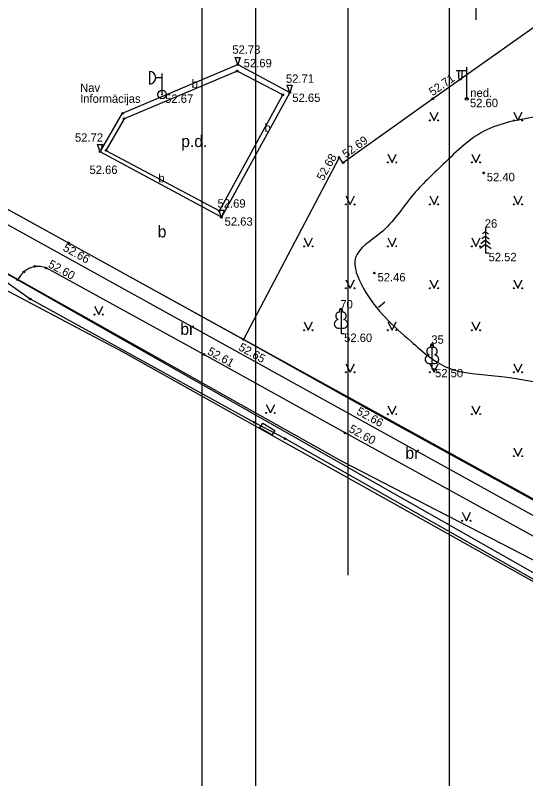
# Model space of a CAD drawing. Extents: x 619806 to 620082, y 405176 to 405386.
# Drawn here: x 619922.53 to 619952.97, y 405203.29 to 405248.76 of the extents above; entities that cross this region are included whole.
import ezdxf

# ---------------------------------------------------------------- set-up
doc = ezdxf.new("R2010")
doc.units = 0
for name, color, linetype in [('APGR_SARK_####_####_#', 7, 'Continuous'), ('APGS_ELEM_####_####_#', 7, 'Continuous'), ('APGS_ELEM_####_TKST_#', 7, 'Continuous'), ('APGS_VADP_ZSPR_####_#', 7, 'Continuous'), ('BUVE_BDET_####_####_#', 7, 'Continuous'), ('BUVE_BDET_####_TKST_#', 7, 'Continuous'), ('CELI_CMAL_####_####_#', 7, 'Continuous'), ('CELI_CSEG_####_TKST_#', 7, 'Continuous'), ('CELI_SEGL_####_####_#', 7, 'Continuous'), ('GEOD_ELEM_####_####_#', 7, 'Continuous'), ('RAMI_PLAN_####_TKST_#', 7, 'Continuous'), ('RAMI_UZMR_####_####_#', 7, 'Continuous'), ('RELJ_AATZ_####_TKST_#', 7, 'Continuous'), ('RELJ_ELEM_####_####_#', 7, 'Continuous'), ('RELJ_HORZ_PAMT_####_#', 7, 'Continuous'), ('ROBZ_UZMR_####_####_#', 7, 'Continuous'), ('SAKK_KKAN_####_####_#', 7, 'Continuous'), ('SAKT_VADP_KABE_####_#', 7, 'Continuous'), ('TERT_DIAM_####_TKST_#', 7, 'Continuous'), ('TERT_ELEM_####_####_#', 7, 'Continuous'), ('TERT_IZMT_####_TKST_#', 7, 'Continuous')]:
    doc.layers.add(name, color=color, linetype=linetype)

msp = doc.modelspace()

# ---------------------------------------------------------------- linework, layer by layer
at = {"layer": 'APGR_SARK_####_####_#'}
msp.add_lwpolyline([(619990.053, 405197.403), (619966.019, 405209.806), (619941.986, 405222.21), (619880.273, 405256.839), (619818.56, 405291.467)], dxfattribs=at)
at = {"layer": 'APGS_ELEM_####_####_#'}
for p, q in [((619949.453, 405245.456), (619948.818, 405245.451)), ((619948.953, 405245.452), (619948.953, 405245.06)), ((619949.163, 405245.454), (619949.163, 405245.06)), ((619949.453, 405243.789), (619949.453, 405245.672)), ((619930.535, 405245.42), (619930.535, 405244.67)), ((619931.285, 405245.045), (619930.91, 405245.045)), ((619931.285, 405244.045), (619931.285, 405245.295))]:
    msp.add_line(p, q, dxfattribs=at)
msp.add_lwpolyline([(619937.841, 405223.763), (619937.12, 405224.195), (619937.283, 405224.465), (619938.003, 405224.033)], close=True, dxfattribs=at)
for centre, radius in [((619931.285, 405244.045), 0.25), ((619931.285, 405244.045), 0.0225), ((619949.453, 405243.789), 0.09)]:
    msp.add_circle(centre, radius, dxfattribs=at)
msp.add_arc((619930.535, 405245.045), 0.375, 270, 90, dxfattribs=at)
msp.add_ellipse((619949.058, 405245.06), major_axis=(0, 0.151), ratio=0.695971, start_param=1.570796, end_param=4.712389, dxfattribs=at)
at = {"layer": 'APGS_VADP_ZSPR_####_#'}
msp.add_lwpolyline([(619827.279, 405290.766), (619828.233, 405290.484), (619831.689, 405284.666), (619835.137, 405280.637), (619844.802, 405275.519), (619857.367, 405269.037), (619864.044, 405264.897), (619871.373, 405258.791), (619881.17, 405253.384), (619884.232, 405252.778), (619898.622, 405244.594), (619910.805, 405239.254), (619917.273, 405236.249), (619923.426, 405231.863), (619936.8, 405224.512), (619938.618, 405223.547), (619972.929, 405204.127)], dxfattribs=at)
at = {"layer": 'BUVE_BDET_####_####_#'}
for p, q in [((619928.934, 405242.924), (619935.8, 405245.823)), ((619935.8, 405245.823), (619938.901, 405244.168)), ((619935.765, 405245.437), (619929.018, 405242.597)), ((619938.484, 405244.025), (619935.765, 405245.437)), ((619938.901, 405244.168), (619934.828, 405236.728)), ((619934.7, 405237.11), (619938.484, 405244.025)), ((619927.594, 405240.635), (619928.934, 405242.924)), ((619929.018, 405242.597), (619927.94, 405240.715)), ((619934.828, 405236.728), (619927.594, 405240.635)), ((619927.94, 405240.715), (619934.7, 405237.11))]:
    msp.add_line(p, q, dxfattribs=at)
at = {"layer": 'CELI_CMAL_####_####_#'}
for points in [[(619982.283, 405204.018), (619982.381, 405205.526), (619981.404, 405213.543), (619980.879, 405217.395), (619980.193, 405224.262), (619979.707, 405227.554), (619978.646, 405227.479), (619978.06, 405232.469), (619979.052, 405232.579), (619978.008, 405242.924), (619976.591, 405255.672), (619975.781, 405263.512), (619969.844, 405259.482), (619963.066, 405254.752), (619955.624, 405249.587), (619947.422, 405243.791), (619942.081, 405239.98), (619941.835, 405240.299), (619936.133, 405229.455), (619943.441, 405225.387), (619954.092, 405219.528), (619965.106, 405213.442), (619974.994, 405207.99), (619982.283, 405204.018)], [(619978.752, 405201.011), (619979.424, 405202.021), (619979.564, 405202.436), (619979.607, 405202.714), (619979.55, 405203.052), (619979.303, 405203.399), (619978.982, 405203.652), (619974.243, 405206.289), (619963.757, 405212.03), (619953.443, 405217.716), (619942.194, 405223.883), (619933.774, 405228.562), (619924.371, 405233.711), (619924.04, 405233.797), (619923.689, 405233.804), (619923.346, 405233.679), (619923.051, 405233.473), (619922.837, 405233.256), (619922.669, 405233.014)]]:
    msp.add_lwpolyline(points, dxfattribs=at)
at = {"layer": 'CELI_SEGL_####_####_#'}
msp.add_lwpolyline([(619903.949, 405247.281), (619909.925, 405243.896), (619925.717, 405235.208), (619936.133, 405229.455)], dxfattribs=at)
at = {"layer": 'GEOD_ELEM_####_####_#'}
msp.add_line((619950, 405250), (619950, 405248.5), dxfattribs=at)
at = {"layer": 'RAMI_PLAN_####_TKST_#'}
msp.add_line((619942.357, 405361.716), (619942.357, 405215.404), dxfattribs=at)
for points in [[(619933.685, 405385.595), (620082.185, 405385.595), (620082.185, 405175.595), (619933.685, 405175.595)], [(619805.793, 405180.095), (619805.793, 405373.209), (619948.393, 405373.209), (619948.393, 405180.095)], [(619936.885, 405180.095), (619936.885, 405373.209), (620079.485, 405373.209), (620079.485, 405180.095)]]:
    msp.add_lwpolyline(points, close=True, dxfattribs=at)
at = {"layer": 'RAMI_UZMR_####_####_#'}
msp.add_lwpolyline([(619874.687, 405324.979), (619926.719, 405349.544), (619966.669, 405369.042), (620021.738, 405292.03), (620049.703, 405275.476), (620026.189, 405242.287), (620012.147, 405222.917), (619996.603, 405200.928), (619989.997, 405199.173), (619982.328, 405199.155), (619922.669, 405233.014), (619882.137, 405255.756), (619859.084, 405268.056), (619820.646, 405290.715), (619813.744, 405295.206), (619820.645, 405298.752)], close=True, dxfattribs=at)
at = {"layer": 'RELJ_ELEM_####_####_#'}
for points in [[(619935.65, 405246.256), (619935.95, 405246.256), (619935.8, 405245.823)], [(619938.751, 405244.601), (619939.051, 405244.601), (619938.901, 405244.168)], [(619927.444, 405241.068), (619927.744, 405241.068), (619927.594, 405240.635)], [(619934.678, 405237.161), (619934.978, 405237.161), (619934.828, 405236.728)]]:
    msp.add_lwpolyline(points, close=True, dxfattribs=at)
for centre in [(619935.765, 405245.437), (619935.8, 405245.823), (619938.901, 405244.168), (619938.484, 405244.025), (619947.422, 405243.791), (619928.934, 405242.924), (619929.018, 405242.597), (619927.594, 405240.635), (619927.94, 405240.715), (619941.835, 405240.299), (619942.081, 405239.98), (619950.457, 405239.376), (619934.7, 405237.11), (619934.828, 405236.728), (619925.717, 405235.208), (619923.689, 405233.804), (619924.371, 405233.711), (619923.051, 405233.473), (619943.942, 405233.41), (619922.669, 405233.014), (619923.426, 405231.863), (619936.133, 405229.455), (619933.774, 405228.562), (619943.441, 405225.387), (619936.8, 405224.512), (619942.194, 405223.883), (619938.618, 405223.547)]:
    msp.add_circle(centre, 0.05, dxfattribs=at)
at = {"layer": 'RELJ_HORZ_PAMT_####_#'}
msp.add_line((619944.568, 405231.67), (619944.183, 405231.35), dxfattribs=at)
msp.add_spline([(619952.192, 405242.46), (619958.269, 405245.178), (619960.212, 405247.147), (619962.71, 405245.388), (619969.834, 405240.326), (619973.191, 405239.787), (619973.537, 405236.062), (619972.621, 405231.011), (619971.007, 405227.497), (619970.308, 405225.195), (619972.877, 405224.18), (619975.834, 405223.443), (619975.125, 405220.25), (619977.669, 405218.792), (619978.775, 405216.928), (619978.459, 405213.841), (619976.501, 405213.003), (619972.992, 405212.359), (619969.535, 405213.328), (619966.616, 405215.931), (619967.251, 405218.057), (619966.078, 405220.067), (619963.269, 405223.678), (619959.906, 405226.02), (619956.916, 405226.372), (619951.315, 405227.272), (619948.301, 405227.78), (619946.134, 405229.326), (619943.292, 405232.49), (619942.821, 405234.331), (619944.296, 405235.783), (619946.209, 405238.021), (619948.046, 405239.888), (619950.691, 405241.967), (619952.192, 405242.46)], degree=3, dxfattribs=at)
at = {"layer": 'ROBZ_UZMR_####_####_#'}
for p, q in [((619936.15, 405229.445), (619903.919, 405247.191)), ((619982.318, 405204.025), (619936.15, 405229.445))]:
    msp.add_line(p, q, dxfattribs=at)
at = {"layer": 'SAKK_KKAN_####_####_#'}
msp.add_line((619979.31, 405204.647), (619918.714, 405238.138), dxfattribs=at)
at = {"layer": 'SAKT_VADP_KABE_####_#'}
msp.add_lwpolyline([(619817.668, 405301.762), (619818.308, 405291.251), (619820.058, 405288.244), (619821.78, 405286.435), (619865.996, 405262.382), (619894.538, 405246.913), (619928.954, 405228.717), (619988.18, 405195.595)], dxfattribs=at)
at = {"layer": 'TERT_ELEM_####_####_#'}
for p, q in [((619947.25, 405243), (619947.5, 405242.5)), ((619947.5, 405242.5), (619947.75, 405243)), ((619952.25, 405243), (619952.5, 405242.5)), ((619952.5, 405242.5), (619952.75, 405243)), ((619944.75, 405240.5), (619945, 405240)), ((619945, 405240), (619945.25, 405240.5)), ((619949.75, 405240.5), (619950, 405240)), ((619950, 405240), (619950.25, 405240.5)), ((619942.25, 405238), (619942.5, 405237.5)), ((619942.5, 405237.5), (619942.75, 405238)), ((619947.25, 405238), (619947.5, 405237.5)), ((619947.5, 405237.5), (619947.75, 405238)), ((619952.25, 405238), (619952.5, 405237.5)), ((619952.5, 405237.5), (619952.75, 405238)), ((619950.562, 405236.113), (619950.562, 405234.613)), ((619939.75, 405235.5), (619940, 405235)), ((619940, 405235), (619940.25, 405235.5)), ((619944.75, 405235.5), (619945, 405235)), ((619945, 405235), (619945.25, 405235.5)), ((619949.75, 405235.5), (619950, 405235)), ((619950, 405235), (619950.25, 405235.5)), ((619950.562, 405235.613), (619950.346, 405235.455)), ((619950.562, 405235.863), (619950.386, 405235.735)), ((619950.562, 405235.863), (619950.736, 405235.735)), ((619950.562, 405235.613), (619950.778, 405235.455)), ((619950.562, 405235.113), (619950.23, 405234.869)), ((619950.562, 405235.363), (619950.284, 405235.159)), ((619950.562, 405235.363), (619950.84, 405235.159)), ((619950.562, 405235.113), (619950.896, 405234.869)), ((619950.562, 405234.613), (619950.762, 405234.613)), ((619942.25, 405233), (619942.5, 405232.5)), ((619942.5, 405232.5), (619942.75, 405233)), ((619947.25, 405233), (619947.5, 405232.5)), ((619947.5, 405232.5), (619947.75, 405233)), ((619952.25, 405233), (619952.5, 405232.5)), ((619952.5, 405232.5), (619952.75, 405233)), ((619927.26, 405231.435), (619927.51, 405230.935)), ((619927.51, 405230.935), (619927.76, 405231.435)), ((619939.75, 405230.5), (619940, 405230)), ((619940, 405230), (619940.25, 405230.5)), ((619944.75, 405230.5), (619945, 405230)), ((619945, 405230), (619945.25, 405230.5)), ((619949.75, 405230.5), (619950, 405230)), ((619950, 405230), (619950.25, 405230.5)), ((619941.953, 405230.151), (619941.953, 405229.804)), ((619941.953, 405229.804), (619942.153, 405229.804)), ((619942.25, 405228), (619942.5, 405227.5)), ((619942.5, 405227.5), (619942.75, 405228)), ((619947.25, 405228), (619947.5, 405227.5)), ((619947.374, 405228.045), (619947.374, 405227.698)), ((619947.5, 405227.5), (619947.75, 405228)), ((619952.25, 405228), (619952.5, 405227.5)), ((619952.5, 405227.5), (619952.75, 405228)), ((619947.374, 405227.698), (619947.574, 405227.698)), ((619937.499, 405225.578), (619937.749, 405225.078)), ((619937.749, 405225.078), (619937.999, 405225.578)), ((619944.75, 405225.5), (619945, 405225)), ((619945, 405225), (619945.25, 405225.5)), ((619949.75, 405225.5), (619950, 405225)), ((619950, 405225), (619950.25, 405225.5)), ((619952.25, 405223), (619952.5, 405222.5)), ((619952.5, 405222.5), (619952.75, 405223)), ((619949.178, 405219.158), (619949.428, 405218.658)), ((619949.428, 405218.658), (619949.678, 405219.158))]:
    msp.add_line(p, q, dxfattribs=at)
for points in [[(619941.953, 405231.304), (619941.953, 405230.151)], [(619942.043, 405231.072), (619942.042, 405231.073)], [(619947.374, 405229.198), (619947.374, 405228.045)], [(619947.464, 405228.966), (619947.463, 405228.967)]]:
    msp.add_lwpolyline(points, dxfattribs=at)
for centre, radius in [((619947.25, 405242.5), 0.028), ((619947.75, 405242.5), 0.0263), ((619952.25, 405242.5), 0.028), ((619952.75, 405242.5), 0.0263), ((619944.75, 405240), 0.028), ((619945.25, 405240), 0.0263), ((619949.75, 405240), 0.028), ((619950.25, 405240), 0.0263), ((619942.25, 405237.5), 0.028), ((619942.75, 405237.5), 0.0263), ((619947.25, 405237.5), 0.028), ((619947.75, 405237.5), 0.0263), ((619952.25, 405237.5), 0.028), ((619952.75, 405237.5), 0.0263), ((619939.75, 405235), 0.028), ((619940.25, 405235), 0.0263), ((619944.75, 405235), 0.028), ((619945.25, 405235), 0.0263), ((619949.75, 405235), 0.028), ((619950.25, 405235), 0.0263), ((619942.25, 405232.5), 0.028), ((619942.75, 405232.5), 0.0263), ((619947.25, 405232.5), 0.028), ((619947.75, 405232.5), 0.0263), ((619952.25, 405232.5), 0.028), ((619952.75, 405232.5), 0.0263), ((619927.26, 405230.935), 0.028), ((619927.76, 405230.935), 0.0263), ((619939.75, 405230), 0.028), ((619940.25, 405230), 0.0263), ((619944.75, 405230), 0.028), ((619945.25, 405230), 0.0263), ((619949.75, 405230), 0.028), ((619950.25, 405230), 0.0263), ((619942.25, 405227.5), 0.028), ((619942.75, 405227.5), 0.0263), ((619947.25, 405227.5), 0.028), ((619947.75, 405227.5), 0.0263), ((619952.25, 405227.5), 0.028), ((619952.75, 405227.5), 0.0263), ((619937.499, 405225.077), 0.028), ((619937.999, 405225.077), 0.0263), ((619944.75, 405225), 0.028), ((619945.25, 405225), 0.0263), ((619949.75, 405225), 0.028), ((619950.25, 405225), 0.0263), ((619952.25, 405222.5), 0.028), ((619952.75, 405222.5), 0.0263), ((619949.178, 405218.657), 0.028), ((619949.678, 405218.657), 0.0263)]:
    msp.add_circle(centre, radius, dxfattribs=at)
for centre, major_axis, ratio, start_param, end_param in [((619941.825, 405230.859), (-0.039, -0.212), 0.861323, 3.141593, 6.283185), ((619941.953, 405231.154), (0, -0.15), 0.707107, 3.14537, 5.287485), ((619941.953, 405231.154), (0, -0.15), 0.707107, 0.995701, 3.137816), ((619942.081, 405230.859), (0.039, -0.212), 0.861323, 0, 3.141593), ((619941.863, 405230.397), (0.307, 0.095), 0.814445, 1.570796, 4.752015), ((619942.043, 405230.397), (-0.307, 0.095), 0.814445, 1.531171, 4.712389), ((619947.374, 405229.048), (0, -0.15), 0.707107, 3.14537, 5.287485), ((619947.374, 405229.048), (0, -0.15), 0.707107, 0.995701, 3.137816), ((619947.246, 405228.753), (-0.039, -0.212), 0.861323, 3.141593, 6.283185), ((619947.502, 405228.753), (0.039, -0.212), 0.861323, 0, 3.141593), ((619947.284, 405228.291), (0.307, 0.095), 0.814445, 1.570796, 4.752015), ((619947.464, 405228.291), (-0.307, 0.095), 0.814445, 1.531171, 4.712389)]:
    msp.add_ellipse(centre, major_axis=major_axis, ratio=ratio, start_param=start_param, end_param=end_param, dxfattribs=at)

# ---------------------------------------------------------------- texts
at = {"layer": 'APGS_ELEM_####_TKST_#'}
for s, p in [('Nav', (619926.402, 405244.199)), ('ned.', (619949.658, 405243.897)), ('Informācijas', (619926.402, 405243.549))]:
    msp.add_text(s, height=0.5, dxfattribs=at).set_placement(p)
at = {"layer": 'BUVE_BDET_####_TKST_#'}
for p in [(619933.052, 405244.434), (619937.391, 405241.819), (619931.066, 405238.812)]:
    msp.add_text('b', height=0.5, dxfattribs=at).set_placement(p)
at = {"layer": 'CELI_CSEG_####_TKST_#'}
for s, p in [('b', (619931.024, 405235.531)), ('br', (619932.375, 405229.726)), ('br', (619945.791, 405222.338))]:
    msp.add_text(s, height=0.7, dxfattribs=at).set_placement(p)
at = {"layer": 'RELJ_AATZ_####_TKST_#'}
for s, p in [(' 52.73', (619935.288, 405246.472)), (' 52.69', (619935.969, 405245.665)), (' 52.71', (619938.484, 405244.74)), (' 52.65', (619938.863, 405243.599)), (' 52.67', (619931.285, 405243.545)), (' 52.60', (619949.453, 405243.289)), (' 52.72', (619925.908, 405241.232)), (' 52.66', (619926.774, 405239.311)), (' 52.40', (619950.457, 405238.876)), (' 52.69', (619934.406, 405237.305)), (' 52.63', (619934.828, 405236.228)), (' 52.52', (619950.562, 405234.113)), (' 52.46', (619943.942, 405232.91)), (' 52.60', (619941.953, 405229.304)), (' 52.50', (619947.374, 405227.198))]:
    msp.add_text(s, height=0.5, dxfattribs=at).set_placement(p)
for s, rotation, p in [(' 52.71', 34.8095, (619947.256, 405243.832)), (' 52.69', 35.5093, (619942.097, 405240.128)), (' 52.68', 60.5706, (619940.808, 405238.715)), (' 52.66', 331.0871, (619925.172, 405234.859)), (' 52.60', 331.2953, (619924.285, 405233.879)), (' 52.65', 330.8975, (619935.639, 405228.937)), (' 52.61', 330.939, (619933.781, 405228.685)), (' 52.66', 331.1853, (619942.67, 405225.111)), (' 52.60', 331.2673, (619942.211, 405224.064))]:
    msp.add_text(s, height=0.5, rotation=rotation, dxfattribs=at).set_placement(p)
at = {"layer": 'TERT_DIAM_####_TKST_#'}
for s, p in [(' 26', (619950.337, 405236.113)), (' 70', (619941.728, 405231.304)), (' 35', (619947.149, 405229.198))]:
    msp.add_text(s, height=0.5, dxfattribs=at).set_placement(p)
at = {"layer": 'TERT_IZMT_####_TKST_#'}
msp.add_text('p.d.', height=0.7, dxfattribs=at).set_placement((619932.428, 405240.914))

doc.saveas('drawing.dxf')
